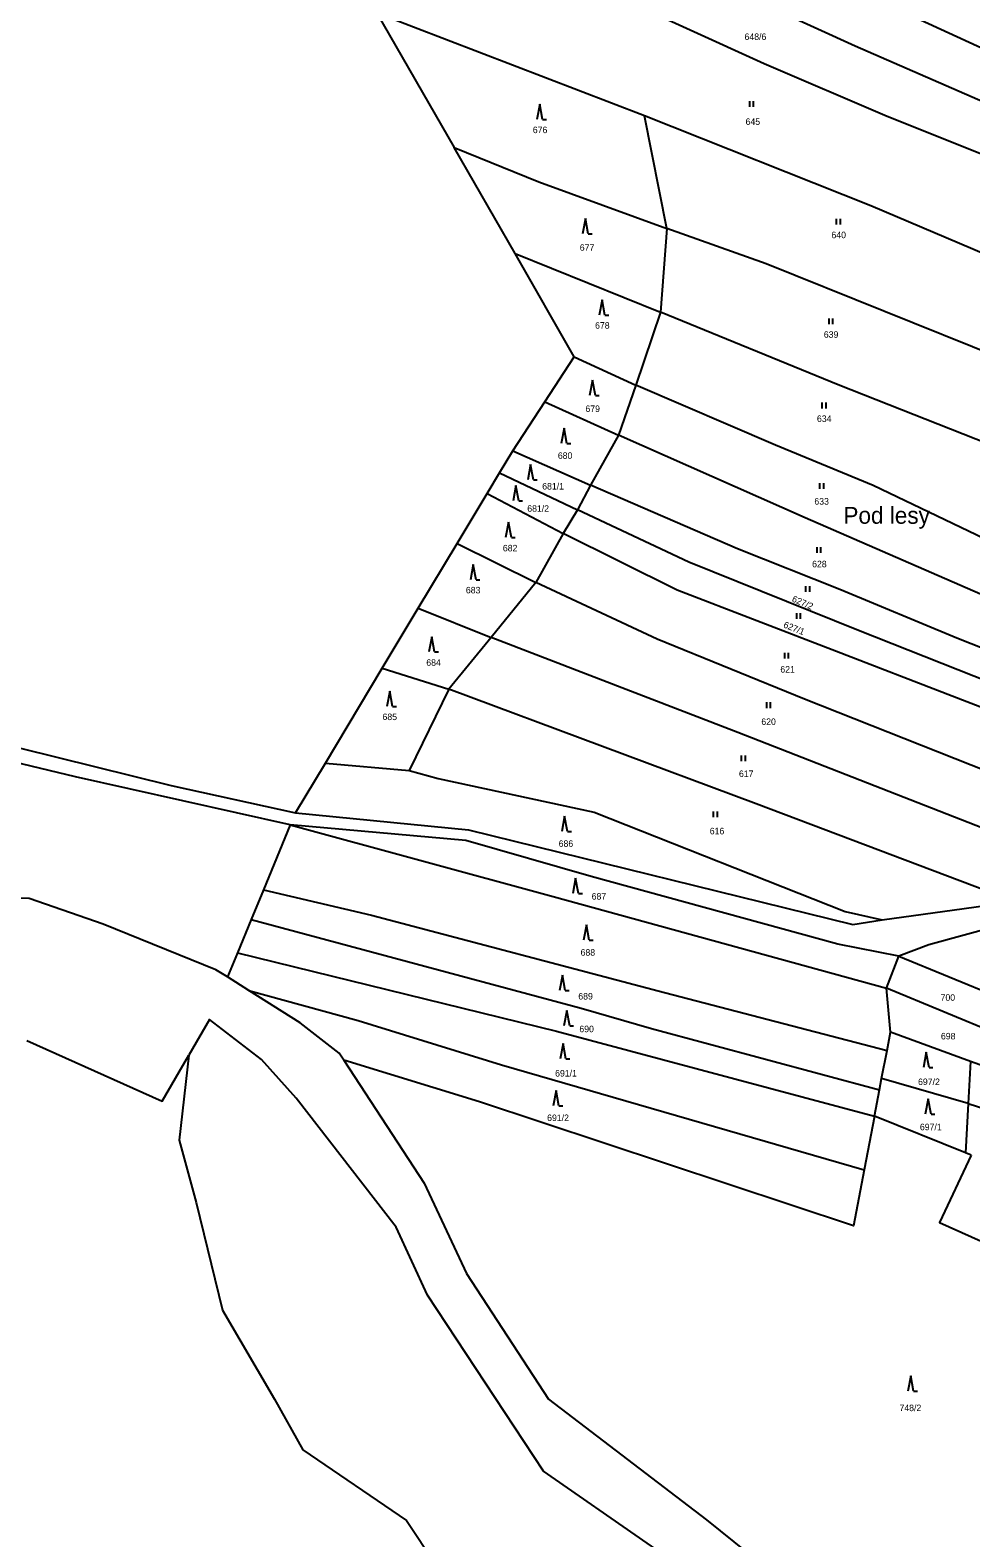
# Model space of a CAD drawing. Extents: x -7483133 to -743169, y -11317770 to -1127091.
# Drawn here: x -748944.8 to -748699.3, y -1131157.3 to -1130763.6 of the extents above; entities that cross this region are included whole.
import ezdxf

# ---------------------------------------------------------------- set-up
doc = ezdxf.new("R2010")
doc.units = 0
for name, color, linetype in [('Hranice parcel', 7, 'Continuous'), ('Parcelní čísla', 7, 'Continuous'), ('Pop  PČ popisy', 7, 'Continuous'), ('Značky kultur', 7, 'Continuous')]:
    doc.layers.add(name, color=color, linetype=linetype)

msp = doc.modelspace()

# ---------------------------------------------------------------- linework, layer by layer
at = {"layer": 'Hranice parcel'}
for p, q in [((-748854.35, -1130759.21), (-748834.13, -1130794.29)), ((-748784.49, -1130785.99), (-748853.32, -1130759.59)), ((-748778.58, -1130815.45), (-748784.49, -1130785.99)), ((-748818.2, -1130821.92), (-748834.13, -1130794.29)), ((-748778.58, -1130815.45), (-748780.28, -1130837.27)), ((-748818.2, -1130821.92), (-748780.28, -1130837.27)), ((-748802.84, -1130848.91), (-748818.2, -1130821.92)), ((-748780.28, -1130837.27), (-748786.7, -1130856.35)), ((-748810.46, -1130860.65), (-748802.84, -1130848.91)), ((-748802.84, -1130848.91), (-748786.7, -1130856.35)), ((-748786.7, -1130856.35), (-748791.23, -1130869.37)), ((-748818.81, -1130873.52), (-748810.46, -1130860.65)), ((-748810.46, -1130860.65), (-748791.23, -1130869.37)), ((-748791.23, -1130869.37), (-748798.57, -1130882.46)), ((-748822.26, -1130879.25), (-748818.81, -1130873.52)), ((-748818.81, -1130873.52), (-748798.57, -1130882.46)), ((-748825.52, -1130884.67), (-748822.26, -1130879.25)), ((-748822.26, -1130879.25), (-748801.95, -1130888.88)), ((-748833.33, -1130897.65), (-748825.52, -1130884.67)), ((-748825.52, -1130884.67), (-748805.64, -1130895.06)), ((-748798.57, -1130882.46), (-748801.95, -1130888.88)), ((-748801.95, -1130888.88), (-748805.64, -1130895.06)), ((-748843.53, -1130914.6), (-748833.33, -1130897.65)), ((-748833.33, -1130897.65), (-748812.83, -1130907.88)), ((-748805.64, -1130895.06), (-748812.83, -1130907.88)), ((-748812.83, -1130907.88), (-748824.49, -1130922.2)), ((-748852.94, -1130930.24), (-748843.53, -1130914.6)), ((-748843.53, -1130914.6), (-748824.49, -1130922.2)), ((-748824.49, -1130922.2), (-748835.48, -1130935.7)), ((-748867.73, -1130955.03), (-748852.94, -1130930.24)), ((-748852.94, -1130930.24), (-748835.48, -1130935.7)), ((-748835.48, -1130935.7), (-748845.89, -1130956.91)), ((-748875.49, -1130968.04), (-748867.73, -1130955.03)), ((-748867.73, -1130955.03), (-748845.89, -1130956.91)), ((-748876.9, -1130971.17), (-748883.92, -1130988.13)), ((-748883.92, -1130988.13), (-748887.11, -1130995.84)), ((-748722.45, -1130995.95), (-748687.86, -1130991.16)), ((-748887.11, -1130995.84), (-748890.71, -1131004.53)), ((-748890.71, -1131004.53), (-748893.32, -1131010.83)), ((-748721.27, -1131013.77), (-748718.11, -1131005.41)), ((-748718.11, -1131005.41), (-748691.78, -1131016.23)), ((-748887.67, -1131014.39), (-748893.32, -1131010.83)), ((-748691.89, -1131026.01), (-748721.27, -1131013.77)), ((-748720.21, -1131025.25), (-748721.27, -1131013.77)), ((-748721.16, -1131030.03), (-748720.21, -1131025.25)), ((-748699.34, -1131032.91), (-748720.21, -1131025.25)), ((-748722.61, -1131037.34), (-748721.16, -1131030.03)), ((-748699.34, -1131032.91), (-748700.01, -1131043.9)), ((-748691.34, -1131035.8), (-748699.34, -1131032.91)), ((-748723.16, -1131040.37), (-748722.61, -1131037.34)), ((-748700.01, -1131043.9), (-748722.61, -1131037.34)), ((-748724.39, -1131047.18), (-748723.16, -1131040.37)), ((-748724.39, -1131047.18), (-748727.08, -1131061.25)), ((-748700.66, -1131056.76), (-748724.39, -1131047.18)), ((-748700.01, -1131043.9), (-748700.66, -1131056.76)), ((-748700.01, -1131043.9), (-748695.07, -1131045.45)), ((-748699.23, -1131057.41), (-748700.66, -1131056.76))]:
    msp.add_line(p, q, dxfattribs=at)
for points in [[(-748656.74, -1130787.3), (-748680.72, -1130775.54), (-748712.39, -1130761.05), (-748780.75, -1130728.31), (-748831.33, -1130705.07), (-748858.25, -1130692.59)], [(-748855.58, -1130710.12), (-748821.23, -1130726.15), (-748767.45, -1130750.32), (-748729.5, -1130767.78), (-748660.26, -1130797.97)], [(-748663.47, -1130808.22), (-748695.21, -1130796.54), (-748721.13, -1130786.22), (-748753.25, -1130772.41), (-748790.9, -1130755.21), (-748826.39, -1130739.6), (-748853.82, -1130727.9)], [(-748679.08, -1130829.15), (-748725.39, -1130809.48), (-748784.49, -1130785.99)], [(-748834.13, -1130794.29), (-748811.99, -1130803.26), (-748778.58, -1130815.45)], [(-748691.29, -1130849.38), (-748752.74, -1130824.68), (-748778.58, -1130815.45)], [(-748691.38, -1130873.01), (-748733.87, -1130856.25), (-748780.28, -1130837.27)], [(-748691.56, -1130898.44), (-748724.77, -1130882.55), (-748750.23, -1130872.02), (-748786.7, -1130856.35)], [(-748676.59, -1130919.71), (-748742.5, -1130891), (-748791.23, -1130869.37)], [(-748674.28, -1130933.73), (-748702.92, -1130922.4), (-748733.51, -1130909.72), (-748760.2, -1130899.08), (-748798.57, -1130882.46)], [(-748672.59, -1130942.59), (-748728.61, -1130920.39), (-748772.9, -1130902.53), (-748801.95, -1130888.88)], [(-748673.99, -1130949.21), (-748734.35, -1130925.92), (-748775.96, -1130909.83), (-748805.64, -1130895.06)], [(-748677.43, -1130964.14), (-748742.72, -1130938.33), (-748781.18, -1130922.64), (-748812.83, -1130907.88)], [(-748686.82, -1130975.66), (-748760.05, -1130947.07), (-748824.49, -1130922.2)], [(-748687.86, -1130991.16), (-748755.34, -1130965.63), (-748835.48, -1130935.7)], [(-749141.24, -1130998.34), (-749051.87, -1130972), (-749016.37, -1130960.85), (-748977.23, -1130943.74), (-748907.96, -1130960.85), (-748875.49, -1130968.04)], [(-748876.9, -1130971.17), (-748932.91, -1130958.6), (-748976.78, -1130948.06), (-749012.79, -1130966.3), (-749130.24, -1131001.82), (-749149.18, -1131007.85), (-749173.79, -1131015.01)], [(-748845.89, -1130956.91), (-748838.31, -1130959.08), (-748797.6, -1130967.82), (-748732.08, -1130993.78), (-748722.45, -1130995.95)], [(-748875.49, -1130968.04), (-748830.4, -1130972.44), (-748730.06, -1130997.2), (-748722.45, -1130995.95)], [(-748718.11, -1131005.41), (-748734.03, -1131002.28), (-748798.34, -1130984.6), (-748831.06, -1130975.19), (-748876.9, -1130971.17)], [(-748876.9, -1130971.17), (-748808.26, -1130989.85), (-748721.27, -1131013.77)], [(-748883.92, -1130988.13), (-748855.69, -1130994.76), (-748779.2, -1131014.91), (-748721.16, -1131030.03)], [(-748893.32, -1131010.83), (-748896.35, -1131008.97), (-748925.75, -1130997.04), (-748945.03, -1130990.41), (-748973.15, -1130989.2), (-748997.61, -1130990.29), (-749095.8, -1131010.5), (-749153.88, -1131013.75), (-749163.47, -1131013.27), (-749173.79, -1131015.01)], [(-748887.11, -1130995.84), (-748800.99, -1131019), (-748782.66, -1131024.35), (-748723.16, -1131040.37)], [(-748691.81, -1130997.44), (-748710.23, -1131002.5), (-748718.11, -1131005.41)], [(-748890.71, -1131004.53), (-748807.39, -1131024.98), (-748724.39, -1131047.18)], [(-748887.67, -1131014.39), (-748859.22, -1131022.19), (-748821.78, -1131033.78), (-748727.08, -1131061.25)], [(-748862.93, -1131032.61), (-748864.13, -1131030.78), (-748874.3, -1131022.82), (-748887.67, -1131014.39)], [(-748392.16, -1131506.55), (-748408.97, -1131492.45), (-748455.93, -1131466.65), (-748484.5, -1131445.39), (-748502.39, -1131429.25), (-748511.24, -1131427.32), (-748518.9, -1131418.34), (-748522.93, -1131412.38), (-748534.82, -1131400.07), (-748560.04, -1131371.4), (-748567.63, -1131359.17), (-748618.14, -1131307.59), (-748670.88, -1131247.89), (-748697.81, -1131219.81), (-748711.66, -1131216.37), (-748756.69, -1131177.5), (-748810.83, -1131139.93), (-748841.05, -1131093.93), (-748849.27, -1131076.16), (-748875.35, -1131042.49), (-748884.41, -1131032.45), (-748897.97, -1131021.96), (-748903.36, -1131031.29)], [(-748945.65, -1131027.42), (-748910.29, -1131043.26), (-748903.36, -1131031.29)], [(-748903.36, -1131031.29), (-748905.89, -1131053.47), (-748901.45, -1131069.76), (-748894.6, -1131097.89), (-748881.04, -1131121.08), (-748873.58, -1131134.34), (-748846.57, -1131152.8), (-748823.65, -1131187.26), (-748755.15, -1131237.08), (-748782.58, -1131345.17), (-748793.36, -1131398.73), (-748812.12, -1131488.8), (-748821.02, -1131580.29), (-748829.28, -1131664.88)], [(-748727.08, -1131061.25), (-748729.9, -1131075.88), (-748827.51, -1131043.45), (-748862.93, -1131032.61)], [(-748862.93, -1131032.61), (-748841.96, -1131064.7), (-748830.94, -1131088.32), (-748809.47, -1131121.13), (-748768.27, -1131152.58), (-748729.51, -1131183.85), (-748683.15, -1131218.97), (-748628.13, -1131281.36), (-748623.2, -1131281.94), (-748602.24, -1131308.39), (-748580.92, -1131332.73), (-748557.75, -1131353.82), (-748544.86, -1131363.16), (-748538.91, -1131375.03), (-748525.17, -1131390.76), (-748504.57, -1131408.29), (-748496.26, -1131416.91), (-748493.37, -1131423.24), (-748472.53, -1131441.85), (-748441.17, -1131464.36)], [(-748699.23, -1131057.41), (-748707.43, -1131074.93), (-748684.92, -1131085.04), (-748649.3, -1131104.79)]]:
    msp.add_lwpolyline(points, dxfattribs=at)
at = {"layer": 'Značky kultur'}
for p, q in [((-748811.81, -1130782.99), (-748812.56, -1130786.99)), ((-748811.06, -1130786.99), (-748811.81, -1130782.99)), ((-748757, -1130783.66), (-748757, -1130782.16)), ((-748756, -1130783.66), (-748756, -1130782.16)), ((-748811.06, -1130786.99), (-748810.06, -1130786.99)), ((-748799.88, -1130812.84), (-748800.63, -1130816.84)), ((-748799.13, -1130816.84), (-748799.88, -1130812.84)), ((-748734.32, -1130814.42), (-748734.32, -1130812.92)), ((-748733.32, -1130814.42), (-748733.32, -1130812.92)), ((-748799.13, -1130816.84), (-748798.13, -1130816.84)), ((-748795.53, -1130834.04), (-748796.28, -1130838.04)), ((-748794.78, -1130838.04), (-748795.53, -1130834.04)), ((-748794.78, -1130838.04), (-748793.78, -1130838.04)), ((-748736.26, -1130840.42), (-748736.26, -1130838.92)), ((-748735.26, -1130840.42), (-748735.26, -1130838.92)), ((-748798.03, -1130855.01), (-748798.78, -1130859.01)), ((-748797.28, -1130859.01), (-748798.03, -1130855.01)), ((-748797.28, -1130859.01), (-748796.28, -1130859.01)), ((-748738.06, -1130862.39), (-748738.06, -1130860.89)), ((-748737.06, -1130862.39), (-748737.06, -1130860.89)), ((-748805.45, -1130867.59), (-748806.2, -1130871.59)), ((-748804.7, -1130871.59), (-748805.45, -1130867.59)), ((-748804.7, -1130871.59), (-748803.7, -1130871.59)), ((-748814.17, -1130877.06), (-748814.92, -1130881.06)), ((-748813.42, -1130881.06), (-748814.17, -1130877.06)), ((-748813.42, -1130881.06), (-748812.42, -1130881.06)), ((-748738.65, -1130883.41), (-748738.65, -1130881.91)), ((-748737.65, -1130883.41), (-748737.65, -1130881.91)), ((-748818.01, -1130882.56), (-748818.76, -1130886.56)), ((-748817.26, -1130886.56), (-748818.01, -1130882.56)), ((-748817.26, -1130886.56), (-748816.26, -1130886.56)), ((-748819.95, -1130892.15), (-748820.7, -1130896.15)), ((-748819.2, -1130896.15), (-748819.95, -1130892.15)), ((-748819.2, -1130896.15), (-748818.2, -1130896.15)), ((-748739.42, -1130900.16), (-748739.42, -1130898.66)), ((-748738.42, -1130900.16), (-748738.42, -1130898.66)), ((-748829.14, -1130903.16), (-748829.89, -1130907.16)), ((-748828.39, -1130907.16), (-748829.14, -1130903.16)), ((-748828.39, -1130907.16), (-748827.39, -1130907.16)), ((-748742.31, -1130910.29), (-748742.31, -1130908.79)), ((-748741.31, -1130910.29), (-748741.31, -1130908.79)), ((-748744.72, -1130917.33), (-748744.72, -1130915.83)), ((-748743.72, -1130917.33), (-748743.72, -1130915.83)), ((-748839.99, -1130922.01), (-748840.74, -1130926.01)), ((-748839.24, -1130926.01), (-748839.99, -1130922.01)), ((-748839.24, -1130926.01), (-748838.24, -1130926.01)), ((-748747.87, -1130927.73), (-748747.87, -1130926.23)), ((-748746.87, -1130927.73), (-748746.87, -1130926.23)), ((-748850.94, -1130936.24), (-748851.69, -1130940.24)), ((-748850.19, -1130940.24), (-748850.94, -1130936.24)), ((-748850.19, -1130940.24), (-748849.19, -1130940.24)), ((-748752.56, -1130940.64), (-748752.56, -1130939.14)), ((-748751.56, -1130940.64), (-748751.56, -1130939.14)), ((-748759.12, -1130954.53), (-748759.12, -1130953.03)), ((-748758.12, -1130954.53), (-748758.12, -1130953.03)), ((-748766.41, -1130969.18), (-748766.41, -1130967.68)), ((-748765.41, -1130969.18), (-748765.41, -1130967.68)), ((-748805.29, -1130968.86), (-748806.04, -1130972.86)), ((-748804.54, -1130972.86), (-748805.29, -1130968.86)), ((-748804.54, -1130972.86), (-748803.54, -1130972.86)), ((-748802.42, -1130985.04), (-748803.17, -1130989.04)), ((-748801.67, -1130989.04), (-748802.42, -1130985.04)), ((-748801.67, -1130989.04), (-748800.67, -1130989.04)), ((-748799.63, -1130997.26), (-748800.38, -1131001.26)), ((-748798.88, -1131001.26), (-748799.63, -1130997.26)), ((-748798.88, -1131001.26), (-748797.88, -1131001.26)), ((-748805.87, -1131010.37), (-748806.62, -1131014.37)), ((-748805.12, -1131014.37), (-748805.87, -1131010.37)), ((-748805.12, -1131014.37), (-748804.12, -1131014.37)), ((-748804.73, -1131019.62), (-748805.48, -1131023.62)), ((-748803.98, -1131023.62), (-748804.73, -1131019.62)), ((-748803.98, -1131023.62), (-748802.98, -1131023.62)), ((-748805.7, -1131028.22), (-748806.45, -1131032.22)), ((-748804.95, -1131032.22), (-748805.7, -1131028.22)), ((-748710.92, -1131030.46), (-748711.67, -1131034.46)), ((-748710.17, -1131034.46), (-748710.92, -1131030.46)), ((-748804.95, -1131032.22), (-748803.95, -1131032.22)), ((-748710.17, -1131034.46), (-748709.17, -1131034.46)), ((-748807.54, -1131040.51), (-748808.29, -1131044.51)), ((-748806.79, -1131044.51), (-748807.54, -1131040.51)), ((-748710.43, -1131042.69), (-748711.18, -1131046.69)), ((-748709.68, -1131046.69), (-748710.43, -1131042.69)), ((-748806.79, -1131044.51), (-748805.79, -1131044.51)), ((-748709.68, -1131046.69), (-748708.68, -1131046.69)), ((-748714.97, -1131114.97), (-748715.72, -1131118.97)), ((-748714.22, -1131118.97), (-748714.97, -1131114.97)), ((-748714.22, -1131118.97), (-748713.22, -1131118.97))]:
    msp.add_line(p, q, dxfattribs=at)

# ---------------------------------------------------------------- texts
at = {"layer": 'Parcelní čísla'}
for s, p in [('648/6', (-748758.34, -1130766.21)), ('645', (-748758.07, -1130788.38)), ('676', (-748813.6, -1130790.54)), ('640', (-748735.66, -1130817.97)), ('677', (-748801.34, -1130821.26)), ('678', (-748797.35, -1130841.59)), ('639', (-748737.65, -1130843.97)), ('679', (-748799.87, -1130863.34)), ('634', (-748739.45, -1130865.94)), ('680', (-748807.06, -1130875.58)), ('681/1', (-748811.15, -1130883.59)), ('633', (-748740.12, -1130887.53)), ('681/2', (-748815.05, -1130889.4)), ('682', (-748821.42, -1130899.74)), ('628', (-748740.7, -1130903.89)), ('683', (-748831.07, -1130910.71)), ('684', (-748841.4, -1130929.61)), ('621', (-748749, -1130931.4)), ('685', (-748852.83, -1130943.79)), ('620', (-748753.96, -1130945.06)), ('617', (-748759.8, -1130958.65)), ('616', (-748767.42, -1130973.61)), ('686', (-748806.85, -1130976.9)), ('687', (-748798.24, -1130990.66)), ('688', (-748801.13, -1131005.3)), ('689', (-748801.73, -1131016.75)), ('700', (-748707.18, -1131017.08)), ('690', (-748801.45, -1131025.29)), ('698', (-748707.09, -1131027.17)), ('691/1', (-748807.78, -1131036.86)), ('697/2', (-748713.06, -1131039.08)), ('691/2', (-748809.86, -1131048.48)), ('697/1', (-748712.58, -1131050.88)), ('748/2', (-748717.91, -1131124.23))]:
    msp.add_text(s, height=1.7, dxfattribs=at).set_placement(p)
for s, rotation, p in [('627/2', 337, (-748746.14, -1130912.78)), ('627/1', 338, (-748748.36, -1130919.52))]:
    msp.add_text(s, height=1.7, rotation=rotation, dxfattribs=at).set_placement(p)
at = {"layer": 'Pop  PČ popisy'}
msp.add_text('Pod lesy', height=4.4, dxfattribs=at).set_placement((-748732.54, -1130892.53))

doc.saveas('drawing.dxf')
